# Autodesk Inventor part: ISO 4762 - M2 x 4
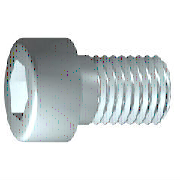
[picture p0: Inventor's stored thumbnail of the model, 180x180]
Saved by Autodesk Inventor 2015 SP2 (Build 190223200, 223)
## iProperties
IsCustomPart: 0
Created: 2012-02
Part Number: ISO 4762 - M2 x 4
Material: Stainless Steel, 440C
Description: Hexagon Socket Head Cap Screw
Document SubType Name: Modeling
Standard: ISO 4762
Designer: rYan
Standard Revision: Fourth edition 2004-03-01
Standards Organization: ISO
Language: en-US
Size Designation: M2 x 4
Categories: <MemberInstance><Categories><Category DisplayName="Fasteners" InternalName="e4da775c-781d-43d5-af7c-5136215cf5a6" Mnemonic="FSTN"><Category DisplayName="Bolts"
Density: 7.75 g/cm^3
Mass: 0.253101 g
Surface Area: 0.751281 cm^2
Volume: 0.0326582 cm^3
Appearance: Halbpoliert
Author: rYan
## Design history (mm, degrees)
sketch "Sketch1"
  geometry: L1 (-0.5, 0)-(4, 0); L2 (4, 0)-(4, 1); L3 (4, 1)-(1, 1); L4 (1, 1)-(0.755, 1); L5 (0.755, 1)-(0, 1); L6 (0, 1)-(0, 1.9); L7 (0, 1.9)-(-2, 1.9); L8 (-2, 1.9)-(-2, 0.866); L9 (-2, 0.866)-(-1, 0.866); L10 (-1, 0.866)-(-0.5, 0); L11 (-3.2, 0)-(5.2, 0) reference; L12 (0, -0.38)-(0, 2.28) reference; L13 (1, 1)-(0, 1)
  constraints: 22 end point, 6 parallel, 2 collinear, 2 perpendicular, 1 horizontal, 1 point on line
  dimensions: "d1" = 3 distance from line of L3.end L2 (= GEL); "d2" = 0.24548 distance of L4.end L3.end (computed from GAL); "d3" = 2 distance between parallel lines of L8 L6 (= KOH); "d4" = 1 distance of L8.end L9.end (= INTI); "d5" = 60 deg angle of L10 L1; "d6" = 2 diameter of L3 L1 (= GD); "d7" = 2 diameter of L5 L1 (= BDM); "d8" = 1.73205 diameter of L9 L1 (= 1.1547 x SW); "d9" = 3.8 diameter of L7 L1 (= KOD); "d26" = 4 distance between parallel lines of L12 L2 (= NLG)
revolve "Body" sketch "Sketch1" stored, may be unused: angle "d10" = 90 deg
sketch "Sketch2"
  geometry: L1 (0, -2.66)-(0, 2.66) reference; L2 (-2.66, 0)-(2.66, 0) reference; L3 (0.866, 0)-(0.433, -0.75); L4 (0.433, -0.75)-(-0.433, -0.75); L5 (-0.433, -0.75)-(-0.866, 0); L6 (-0.866, 0)-(-0.433, 0.75); L7 (-0.433, 0.75)-(0.433, 0.75); L8 (0.433, 0.75)-(0.866, 0); 2 further points
  constraints: 12 end point, 1 coincident, 1 horizontal alignment, 1 point on line, 12 other
extrude "Slot" join sketch "Sketch2" stored distance "d11" = 10; taper "d12" = 0 deg
fillet "Fillet1" dims "d17" = 0.2 (= RR)
feature "Thread" dims "d13" = 3 (= GEL), "d14" = 0
chamfer "Chamfer1" distance "d15" = 0.24538 (= -0.5 x SPD + 0.5 x GD); stored, may be unused: second distance "d16" = 0.24538 (= GUL), angle "d27" = 45 deg
workplane "Work Plane1"
fillet "Fillet2" dims "d30" = 0.1 (= R)
body "Solid1"
other parameters: "GD" = 2 [user parameter; used in 2 equation terms], "NLG" = 4 [user parameter; used in 1 equation term], "GEL" = 3 [user parameter; used in 2 equation terms], "KOD" = 3.8 [user parameter; used in 1 equation term], "KOH" = 2 [user parameter; used in 1 equation term], "INTI" = 1 [user parameter; used in 1 equation term], "GAL" = 0.24538 (= 0.61345 x PTC) [user parameter; used in 1 equation term], "GUL" = 0.24538 (= 0.61345 x PTC) [user parameter; used in 1 equation term], "BDM" = 2 (= NND) [user parameter; used in 1 equation term], "SW" = 1.5 [user parameter; used in 2 equation terms], "RR" = 0.2 [user parameter; used in 1 equation term], "SPD" = 1.50924 (= NND - 1.2269 x PTC) [user parameter; used in 1 equation term], "d19" = 0, "d28" = 0, "d29" = 0, "R" = 0.1 [user parameter; used in 1 equation term], "TOA" = 30 deg [user parameter], "GD1" = 1.50924 (= THREADDIA - 1.2269 x PTC) [user parameter], "THREADDIA" = 2 [user parameter; used in 1 equation term], "FAWI" = 45 deg [user parameter], "TPU" = 25 (computed from PTC) [user parameter], "PTC" = 0.4 [user parameter; used in 5 equation terms], "NND" = 2 [user parameter; used in 2 equation terms], "E0" = 1.7325 (= 1.155 x SW) [user parameter]
